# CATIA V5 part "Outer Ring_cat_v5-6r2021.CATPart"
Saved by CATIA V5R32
Part number: Outer Ring
Bounding box of the stored display mesh (mm): x -99.819 to 99.819, y 0 to 50, z -100 to 100
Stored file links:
  D:\PROJECTS\Project 2022\CATIA V5 6R 2022\Resources\Tutorial Files\c16_catia_v5_6r2022_tut\Bearing\Outer Ring_cat_v5-6r2021.CATPart
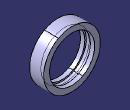
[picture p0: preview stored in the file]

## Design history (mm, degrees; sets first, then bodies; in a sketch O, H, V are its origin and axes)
Body1 (main body)
  Sketch1 on yz-plane, origin (0, 0, 0), H (0, 1, 0), V (0, 0, 1)
    point P1 (0, 80)
    line L1 (0, 80) -> (0, 100)
    line L2 (0, 100) -> (50, 100)
    line L3 (50, 100) -> (50, 80)
    line L4 (50, 80) -> (35, 80)
    line L5 (35, 80) -> (35, 85)
    line L6 (35, 85) -> (15, 85)
    line L7 (15, 85) -> (15, 80)
    point P8 (15, 80)
    line L8 (15, 80) -> (0, 80)
    point P9 (0, 80)
    distance H L8 = 80
    length L2 = 50
    length L5 = 5
    length L8 = 15
    length L4 = 15
    length L1 = 20
    coincidence: P1 V, P8 L4, P9 V, P9 P1
    vertical: L1 V, L3 V, L5 V, L7 V
    horizontal: L2 H, L4 H, L6 H, L8 H
  Shaft1: profile Sketch1, axis Sketch1.H, angle 360
  Plane1: type Offset, RefPlane face of Shaft1 from Sketch1.L5, Offset 10, reversed
  Sketch2 on Plane1, origin (0, 25, 0), H (-1, 0, 0), V (0, 0, 1)
    projected circle E1 centre (0, 0) radius 85 from edge [face of Shaft1 from Sketch1.L6 | face of Shaft1 from Sketch1.L7]
  Point1: type OnCurve, Support Sketch2, RefPoint {extremum Reference Sketch2, Direction (1, 2, 3)}, Length 282.187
